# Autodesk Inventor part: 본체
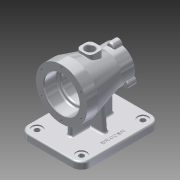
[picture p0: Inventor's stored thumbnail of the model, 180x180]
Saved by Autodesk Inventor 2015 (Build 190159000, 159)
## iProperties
Created: 2021-10
Part Number: 본체
Material: 알루미늄 6061
Document SubType Name: Modeling
Designer: 10259o
Density: 2.7 g/cm^3
Appearance: 알루미늄 - 평지
Mass: 1228.33 g
Surface Area: 906.538 cm^2
Volume: 454.938 cm^3
Author: 10259o
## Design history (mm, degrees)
sketch "스케치1"
  geometry: L1 (0, -99.69)-(0, 0); L2 (31, 0)-(31, -23); L3 (31, -23)-(25, -23); L4 (25, -23)-(25, -70); L5 (25, -70)-(19, -70); L6 (19, -70)-(19, -100); L7 (19, -100)-(29, -100); L8 (29, -100)-(29, -77); L9 (29, -77)-(45, -20); L10 (45, -20)-(45, 0); L11 (45, 0)-(31, 0); 1 further point
  constraints: 22 end point, 5 perpendicular, 1 horizontal, 1 horizontal alignment, 1 midpoint, 1 parallel, 1 vertical
  dimensions: "d0" = 100 distance between parallel lines of L7 L11; "d2" = 38 diameter of L6 L1; "d3" = 30 distance between parallel lines of L5 L7; "d4" = 47 distance between parallel lines of L3 L5; "d5" = 50 diameter of L4 L1; "d6" = 62 diameter of L2 L1; "d7" = 90 diameter of L10 L1; "d8" = 23 distance from line of L8.end L7; "d9" = 20 distance of L9.end L10.end; "d10" = 58 diameter of L8 L1
revolve "회전1" sketch "스케치1" stored, may be unused: angle "d11" = 90 deg
node "작업 평면1"
sketch "스케치2"
  geometry: L1 (55, -120)-(-55, -120); L2 (-55, -120)-(-55, 20); L3 (-55, 20)-(55, 20); L4 (55, 20)-(55, -120); L5 (55, -50)-(-55, -50); L6 (0, 0)-(0, -99.524); 1 further point
  constraints: 12 end point, 3 midpoint, 2 parallel, 1 horizontal, 1 perpendicular, 1 vertical, 1 vertical alignment
  dimensions: "d13" = 140 distance between parallel lines of L1 L3; "d14" = 110 distance of L2.end L3.end; "d15" = 50 distance from line of L5 L6.start
extrude "돌출1" join sketch "스케치2" distance "d16" = 12; taper "d17" = 0 deg
sketch "스케치3"
  geometry: L1 (-4, 13)-(4, 13); L2 (4, 13)-(4, 87); L3 (4, 87)-(-4, 87); L4 (-4, 87)-(-4, 13); L5 (-55, -20)-(-55, 120) reference; L6 (-55, 50)-(55, 50); L7 (55, 120)-(55, -20) reference; 2 further points
  constraints: 10 end point, 3 midpoint, 2 parallel, 1 horizontal, 1 perpendicular, 1 vertical alignment
  dimensions: "d18" = 8 distance of L2.end L3.end; "d19" = 74 distance between parallel lines of L1 L3; "d20" = 37 distance between parallel lines of L3 L6
extrude "돌출2" join sketch "스케치3" stored distance "d21" = 0; taper "d22" = 0 deg
node "작업 평면2"
sketch "스케치4"
  geometry: L1 (0, 12)-(110, 12) reference; L2 (83, 12)-(79.149, 56.019); L3 (79.149, 56.019)-(59, 56.019); L4 (59, 12)-(59, 53.277) reference; L5 (59, 56.019)-(59, 12); 1 further point
  constraints: 6 end point, 2 point on line, 1 collinear, 1 horizontal
  dimensions: "d24" = 95 deg angle of L1 L2; "d25" = 24 distance from line of L4 L2.start
extrude "돌출3" join sketch "스케치4" stored distance "d26" = 8; taper "d27" = 0 deg
node "작업 평면3"
sketch "스케치5"
  geometry: L1 (12.5, -62.5)-(-12.5, -62.5); L2 (-12.5, -62.5)-(-12.5, -37.5); L3 (-12.5, -37.5)-(12.5, -37.5); L4 (12.5, -37.5)-(12.5, -62.5); L5 (-55, -120)-(-55, 20) reference; L6 (-55, -50)-(55, -50); L7 (55, 20)-(55, -120) reference; L8 (55, -120)-(-55, -120) reference; L9 (0, -120)-(0, 20); L10 (-55, 20)-(55, 20) reference; C1 r 8 at (0, -50); 3 further points
  constraints: 12 end point, 7 midpoint, 2 parallel, 2 point on line, 1 centre point, 1 horizontal, 1 perpendicular
  dimensions: "d29" = 25 distance between parallel lines of L4 L2; "d30" = 25 distance of L1.end L2.end; "d31" = 16 diameter of C1
extrude "돌출4" join sketch "스케치5" stored distance "d32" = 8; taper "d33" = 0 deg
sketch "스케치6"
  geometry: C1 r 8 at (0, -50) reference; C2 r 8 at (0, -50); 1 further point
  constraints: 1 centre point, 1 coincident
extrude "돌출5" cut sketch "스케치6" distance "d34" = 31.5; taper "d35" = 0 deg
sketch "스케치7"
  geometry: A1 r 29 centre (0, 0) between (0, 29) and (-6.949, 28.155) reference; A2 r 7 centre (0, 29) between (6.949, 28.155) and (-6.949, 28.155)
  constraints: 5 point on circle, 1 centre point, 1 vertical alignment
  dimensions: "d36" = 14 diameter of A2
extrude "돌출6" join sketch "스케치7" distance "d37" = 15; taper "d38" = 0 deg
sketch "스케치8"
  geometry: A1 r 7 centre (0, 0) between (6.949, -0.845) and (-6.949, -0.845) reference; 1 further point
  constraints: 1 coincident
hole "구멍1" sketch "스케치8" at (0, 0) diameter "d39" = 3.242; stored, may be unused: countersink angle "d43" = 90 deg, drill point angle "d45" = 118 deg; dims "d40" = 9, "d41" = 4, "d42" = 2, "d44" = 11
sketch "스케치9" dims "d49" = 80
  geometry: C1 r 31 at (0, 0) reference; C2 r 45 at (0, 0) reference; 2 further points
  constraints: 2 vertical alignment, 1 coincident, 2 other
hole "구멍2" sketch "스케치9" at (0, 40) diameter "d50" = 3.242; stored, may be unused: countersink angle "d54" = 90 deg, drill point angle "d56" = 118 deg; dims "d51" = 9, "d52" = 4, "d53" = 2, "d55" = 11
sketch "스케치10"
  geometry: L1 (55, 120)-(-55, 120) reference; L2 (-55, 120)-(-55, -20) reference; L3 (-55, -20)-(55, -20) reference; C1 r 9 at (-39, 104); C2 r 9 at (-39, -4); 1 further point
  constraints: 2 centre point, 1 vertical alignment
  dimensions: "d60" = 16 distance from line of L2 C2.centre; "d61" = 16 distance from line of L3 C2.centre; "d62" = 16 distance from line of L1 C1.centre; "d63" = 18 diameter of C1; "d64" = 18 diameter of C2
extrude "돌출7" cut sketch "스케치10" distance "d65" = 2; taper "d66" = 0 deg
sketch "스케치11"
  geometry: C1 r 9 at (0, 0) reference; C2 r 4.5 at (0, 0); C3 r 9 at (0, -108) reference; C4 r 4.5 at (0, -108); 1 further point
  constraints: 2 centre point, 2 coincident
  dimensions: "d67" = 9 diameter of C4; "d68" = 9 diameter of C2
extrude "돌출8" cut sketch "스케치11" stored distance "d69" = 2; taper "d70" = 0 deg
fillet "모깎기1" dims "d71" = 16
fillet "모깎기2" dims "d72" = 3
fillet "모깎기3" dims "d73" = 3
fillet "모깎기4" dims "d74" = 3
fillet "모깎기5" dims "d75" = 3
fillet "모깎기6" dims "d76" = 8
fillet "모깎기7" dims "d77" = 1
chamfer "모따기1" distance "d78" = 1; stored, may be unused: second distance "d79" = 2, angle "d80" = 45 deg
chamfer "모따기2" distance "d81" = 1; stored, may be unused: second distance "d82" = 2, angle "d83" = 45 deg
fillet "모깎기8" dims "d84" = 3
fillet "모깎기9" dims "d85" = 1
fillet "모깎기10" dims "d86" = 3
fillet "모깎기11" dims "d87" = 3
sketch "스케치12"
  geometry: L1 (-52, -4)-(-52, 104) reference; L2 (55, -4)-(55, 104) reference; 3 further points
  constraints: 1 horizontal alignment, 1 midpoint, 1 other
  dimensions: "d88" = 15 distance from line of L2 point (40, 50)
feature "엠보싱1" sketch "스케치12" dims "d13" = 140, "d14" = 110, "d15" = 50, "d89" = 0.5, "d90" = 0
node "솔리드1"
mirror "대칭1"
pattern_circular "원형 패턴1" dims angle "d47" = 360 deg
pattern_circular "원형 패턴2" dims angle "d58" = 360 deg
mirror "대칭2"
other parameters: "d12" = -82, "d28" = 45
